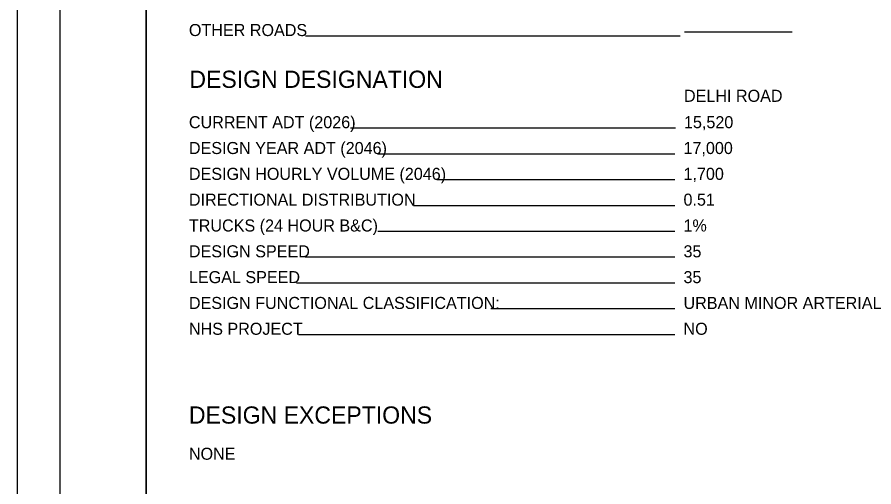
# Model space of a CAD drawing. Extents: x 0 to 34, y -2 to 22.
# Drawn here: x 0 to 9.95, y 5.64 to 11.1 of the extents above; entities that cross this region are included whole.
import ezdxf

# ---------------------------------------------------------------- set-up
doc = ezdxf.new("R2010")
doc.units = 0
for name, color, linetype in [('SH_Border', 7, 'Continuous'), ('SH_Cut_Line', 7, 'Continuous'), ('SH_Data', 7, 'Continuous'), ('SH_Text', 7, 'Continuous')]:
    doc.layers.add(name, color=color, linetype=linetype)

msp = doc.modelspace()

# ---------------------------------------------------------------- linework, layer by layer
at = {"layer": 'SH_Border'}
for points in [[(0.5, 21.5), (1.5, 21.5), (1.5, 0.5), (0.5, 0.5)], [(1.5, 21.5), (33.5, 21.5), (33.5, 0.5), (1.5, 0.5)]]:
    msp.add_lwpolyline(points, close=True, dxfattribs=at)
at = {"layer": 'SH_Cut_Line'}
msp.add_lwpolyline([(0, 0), (34, 0), (34, 22), (0, 22)], close=True, dxfattribs=at)
at = {"layer": 'SH_Data'}
for p, q in [((7.7, 10.8767), (3.3471, 10.8767)), ((9, 10.9223), (7.75, 10.9223)), ((7.6424, 9.8062), (3.871, 9.8062)), ((7.6368, 9.5062), (4.1885, 9.5062)), ((7.6368, 9.2062), (4.8723, 9.2062)), ((7.6368, 8.9062), (4.6037, 8.9062)), ((7.6368, 8.6062), (4.1885, 8.6062)), ((7.6368, 8.3062), (3.346, 8.3062)), ((7.6368, 8.0062), (3.2422, 8.0062)), ((7.6368, 7.7062), (5.5015, 7.7062)), ((7.6368, 7.4062), (3.2669, 7.4062))]:
    msp.add_line(p, q, dxfattribs=at)

# ---------------------------------------------------------------- texts
msp.add_text('DESIGN DESIGNATION', height=0.2, dxfattribs=at).set_placement((2, 10.2747))
at = {"layer": 'SH_Text'}
for s, height, p in [('OTHER ROADS', 0.14, (1.9944, 10.8767)), ('DELHI ROAD', 0.14, (7.7424, 10.1126)), ('CURRENT ADT (2026)', 0.14, (1.9944, 9.8062)), ('15,520  ', 0.14, (7.7424, 9.8062)), ('DESIGN YEAR ADT (2046)', 0.14, (1.9944, 9.5062)), ('17,000  ', 0.14, (7.7368, 9.5062)), ('DESIGN HOURLY VOLUME (2046)', 0.14, (1.9944, 9.2062)), ('1,700  ', 0.14, (7.7368, 9.2062)), ('DIRECTIONAL DISTRIBUTION', 0.14, (1.9944, 8.9062)), ('0.51  ', 0.14, (7.7368, 8.9062)), ('TRUCKS (24 HOUR B&C)', 0.14, (1.9944, 8.6062)), ('1%', 0.14, (7.7368, 8.6062)), ('DESIGN SPEED', 0.14, (1.9944, 8.3062)), ('35 ', 0.14, (7.7368, 8.3062)), ('LEGAL SPEED', 0.14, (1.9944, 8.0062)), ('35 ', 0.14, (7.7368, 8.0062)), ('DESIGN FUNCTIONAL CLASSIFICATION:', 0.14, (1.9944, 7.7062)), ('URBAN MINOR ARTERIAL ', 0.14, (7.7368, 7.7062)), ('NHS PROJECT', 0.14, (1.9944, 7.4062)), ('NO', 0.14, (7.7368, 7.4062)), ('DESIGN EXCEPTIONS', 0.2, (1.9944, 6.3744)), ('NONE', 0.14, (1.9944, 5.9544))]:
    msp.add_text(s, height=height, dxfattribs=at).set_placement(p)

doc.saveas('drawing.dxf')
